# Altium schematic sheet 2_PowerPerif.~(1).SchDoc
size 414 x 293 mm; SheetNumber: 2; SheetTotal: 4
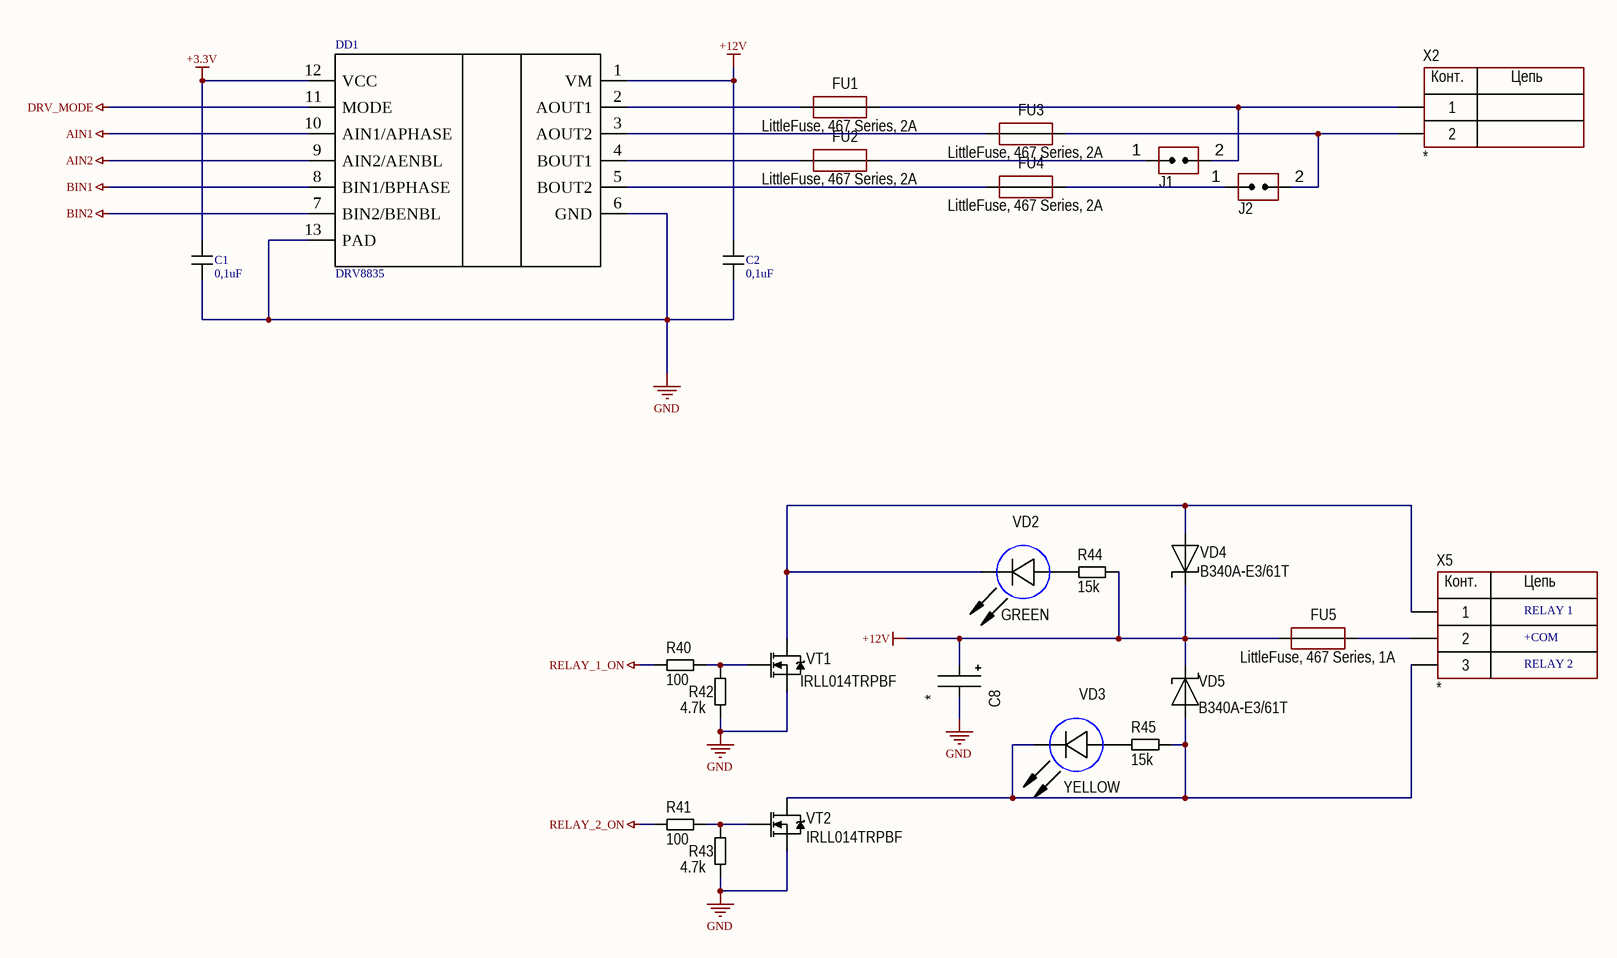
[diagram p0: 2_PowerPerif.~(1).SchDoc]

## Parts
C1  0,1uF  [C_0603]
C2  0,1uF  [C_0603]
C8  *  [D8C3.2H12]
DD1  DRV8835  [WSON12]
FU1  LittleFuse, 467 Series, 2A  [CH0603F]
FU2  LittleFuse, 467 Series, 2A  [CH0603F]
FU3  LittleFuse, 467 Series, 2A  [CH0603F]
FU4  LittleFuse, 467 Series, 2A  [CH0603F]
FU5  LittleFuse, 467 Series, 1A  [CH0603F]
J1  Jumper-2  [CON: PLS-2]  (value not drawn)
J2  Jumper-2  [CON: PLS-2]  (value not drawn)
R40  100  [CH0805R]
R41  100  [CH0805R]
R42  4.7k  [CH0805R]
R43  4.7k  [CH0805R]
R44  15k  [CH0805R]
R45  15k  [CH0805R]
VD2  GREEN  [CH0603LB]
VD3  YELLOW  [CH0603LB]
VD4  B340A-E3/61T  [SMA]
VD5  B340A-E3/61T  [SMA]
VT1  IRLL014TRPBF  [SOT223]
VT2  IRLL014TRPBF  [SOT223]
X2  *  [CON: CWF-2]
X5  *  [CON: 300-03P-5.0]

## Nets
+3.3V: C1.2 DD1.12(VCC)
+12V: C2.2 C8.1 DD1.1(VM) FU5.1 R44.2 VD4.2 VD5.2
AIN1: DD1.10(AIN1/APHASE)
AIN2: DD1.9(AIN2/AENBL)
BIN1: DD1.8(BIN1/BPHASE)
BIN2: DD1.7(BIN2/BENBL)
DRV_MODE: DD1.11(MODE)
GND: C1.1 C2.1 C8.2 DD1.6(GND) DD1.13(PAD) R42.1 R43.1 VT1.3(S) VT2.3(S)
RELAY_1_ON: R40.2
RELAY_2_ON: R41.2
NetDD1_2: DD1.2(AOUT1) FU1.1
NetDD1_3: DD1.3(AOUT2) FU3.1
NetDD1_4: DD1.4(BOUT1) FU2.1
NetDD1_5: DD1.5(BOUT2) FU4.1
NetFU1_2: FU1.2 J1.2(IN) X2.1
NetFU2_2: FU2.2 J1.1(IN)
NetFU3_2: FU3.2 J2.2(IN) X2.2
NetFU4_2: FU4.2 J2.1(IN)
NetFU5_2: FU5.2 X5.2
NetR40_1: R40.1 R42.2 VT1.1(G)
NetR41_1: R41.1 R43.2 VT2.1(G)
NetR44_1: R44.1 VD2.1(A)
NetR45_1: R45.1 VD3.1(A)
NetR45_2: R45.2 VD3.2(C) VD5.1 VT2.2(D) X5.3
NetVD2_2: VD2.2(C) VD4.1 VT1.2(D) X5.1

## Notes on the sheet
- RELAY 1
- +COM
- RELAY 2

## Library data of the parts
C1 C2 = C_SMD
C8 = AlumCap
DD1 = DRV8835: Driver
FU1-FU5 = Fuse
J1 J2 = Jumper-2: Jumper; Manufacturer: China; Model: PLS-2
R40-R45 = Resistor
VD2 VD3 = LED_1
VD4 VD5 = Diod Schottky
VT1 VT2 = N-chanel: Mosfet
X2 = 2-Connector
X5 = 3-Connector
